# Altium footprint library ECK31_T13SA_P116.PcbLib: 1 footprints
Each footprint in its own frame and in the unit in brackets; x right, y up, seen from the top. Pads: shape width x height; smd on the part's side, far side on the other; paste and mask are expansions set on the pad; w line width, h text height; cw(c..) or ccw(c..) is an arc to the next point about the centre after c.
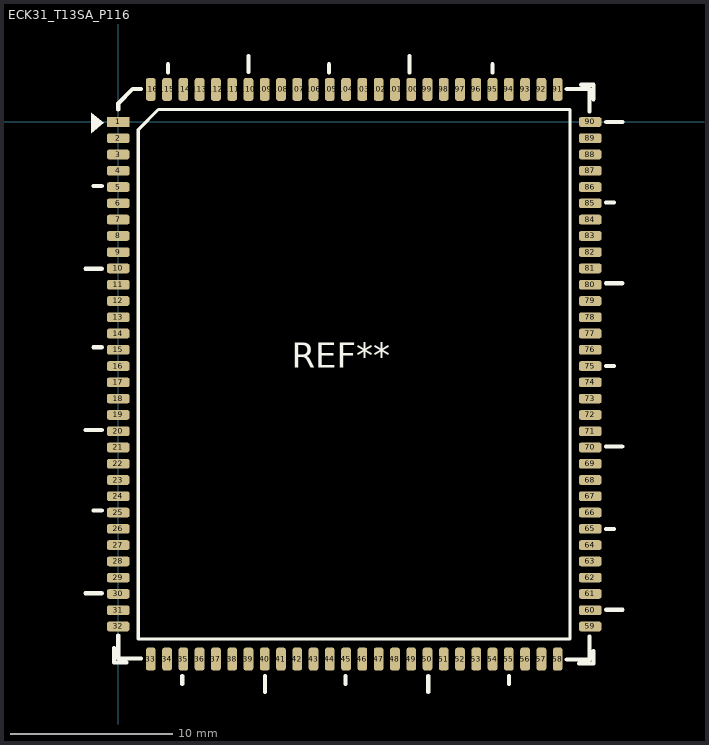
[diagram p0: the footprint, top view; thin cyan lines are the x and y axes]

## ECK31_T13SA_P116 [mm]
pads (116):
  rect 1.4x0.6 smd: 1(0,0)
  rrect50% 1.4x0.6 smd: 2(0,-1) 3(0,-2) 4(0,-3) 5(0,-4) 6(0,-5) 7(0,-6) 8(0,-7) 9(0,-8) 10(0,-9) 11(0,-10) 12(0,-11) 13(0,-12) 14(0,-13) 15(0,-14) 16(0,-15) 17(0,-16) 18(0,-17) 19(0,-18) 20(0,-19) 21(0,-20) 22(0,-21) 23(0,-22) 24(0,-23) 25(0,-24) 26(0,-25) 27(0,-26) 28(0,-27) 29(0,-28) 30(0,-29) 31(0,-30) 32(0,-31) 59(29,-31) 60(29,-30) 61(29,-29) 62(29,-28) 63(29,-27) 64(29,-26) 65(29,-25) 66(29,-24) 67(29,-23) 68(29,-22) 69(29,-21) 70(29,-20) 71(29,-19) 72(29,-18) 73(29,-17) 74(29,-16) 75(29,-15) 76(29,-14) 77(29,-13) 78(29,-12) 79(29,-11) 80(29,-10) 81(29,-9) 82(29,-8) 83(29,-7) 84(29,-6) 85(29,-5) 86(29,-4) 87(29,-3) 88(29,-2) 89(29,-1) 90(29,0)
  rrect50% 0.6x1.4 smd: 33(2,-33) 34(3,-33) 35(4,-33) 36(5,-33) 37(6,-33) 38(7,-33) 39(8,-33) 40(9,-33) 41(10,-33) 42(11,-33) 43(12,-33) 44(13,-33) 45(14,-33) 46(15,-33) 47(16,-33) 48(17,-33) 49(18,-33) 50(19,-33) 51(20,-33) 52(21,-33) 53(22,-33) 54(23,-33) 55(24,-33) 56(25,-33) 57(26,-33) 58(27,-33) 91(27,2) 92(26,2) 93(25,2) 94(24,2) 95(23,2) 96(22,2) 97(21,2) 98(20,2) 99(19,2) 100(18,2) 101(17,2) 102(16,2) 103(15,2) 104(14,2) 105(13,2) 106(12,2) 107(11,2) 108(10,2) 109(9,2) 110(8,2) 111(7,2) 112(6,2) 113(5,2) 114(4,2) 115(3,2) 116(2,2)
Top Overlay:
  region: -0.889,-0.064 -1.651,0.572 -1.651,-0.699
  lines w0.2: 1.235,-31.765 1.235,-0.47 2.47,0.765 27.765,0.765 27.765,-31.765 1.235,-31.765
  lines w0.254: -2.016,-28.956 -1.016,-28.956 ; -2.016,-18.923 -1.016,-18.923 ; -2.016,-9.017 -1.016,-9.017 ; -1.516,-23.876 -1.016,-23.876 ; -1.516,-13.843 -1.016,-13.843 ; -1.516,-3.937 -1.016,-3.937 ; -0.254,-32.322 -0.254,-33.21 0.508,-33.21 ; 0,-31.559 0,-32.956 1.397,-32.956 ; 0,0.762 0,1.016 0,1.143 0.889,2.032 1.397,2.032 ; 3.048,3.048 3.048,3.548 ; 3.937,-34.536 3.937,-34.036 ; 8.001,3.064 8.001,4.064 ; 9.017,-35.036 9.017,-34.036 ; 12.954,3.048 12.954,3.548 ; 13.97,-34.536 13.97,-34.036 ; 17.907,3.048 17.907,4.048 ; 19.05,-35.036 19.05,-34.036 ; 22.987,3.048 22.987,3.548 ; 24.003,-34.536 24.003,-34.036 ; 27.559,-33.02 28.956,-33.02 28.956,-31.623 ; 27.559,2.032 28.956,2.032 28.956,0.635 ; 28.321,-33.274 29.21,-33.274 29.21,-32.512 ; 28.448,2.286 29.21,2.286 29.21,1.397 ; 29.972,-25.019 30.472,-25.019 ; 29.972,-19.939 30.972,-19.939 ; 29.972,-14.986 30.472,-14.986 ; 29.972,-9.906 30.972,-9.906 ; 29.972,-4.953 30.472,-4.953 ; 29.988,-29.972 30.988,-29.972 ; 29.988,0 30.988,0
  text "REF**" at 10.668,-15.113 h1.52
